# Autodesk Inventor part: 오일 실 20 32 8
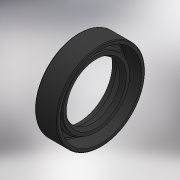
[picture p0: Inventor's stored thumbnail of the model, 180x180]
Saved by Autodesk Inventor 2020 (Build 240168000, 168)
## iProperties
Created: 2024-11
Part Number: 오일 실 20 32 8
Material: 고무
Description: 오일-실
Document SubType Name: Modeling
Designer: 1강의실14
Density: 0.93 g/cm^3
Appearance: 기본값
Author: jhkim
Sending System: Autodesk Inventor 2025
Preprocessor: ST-DEVELOPER v20
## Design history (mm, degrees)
feature "Solid1"
node "솔리드1"
